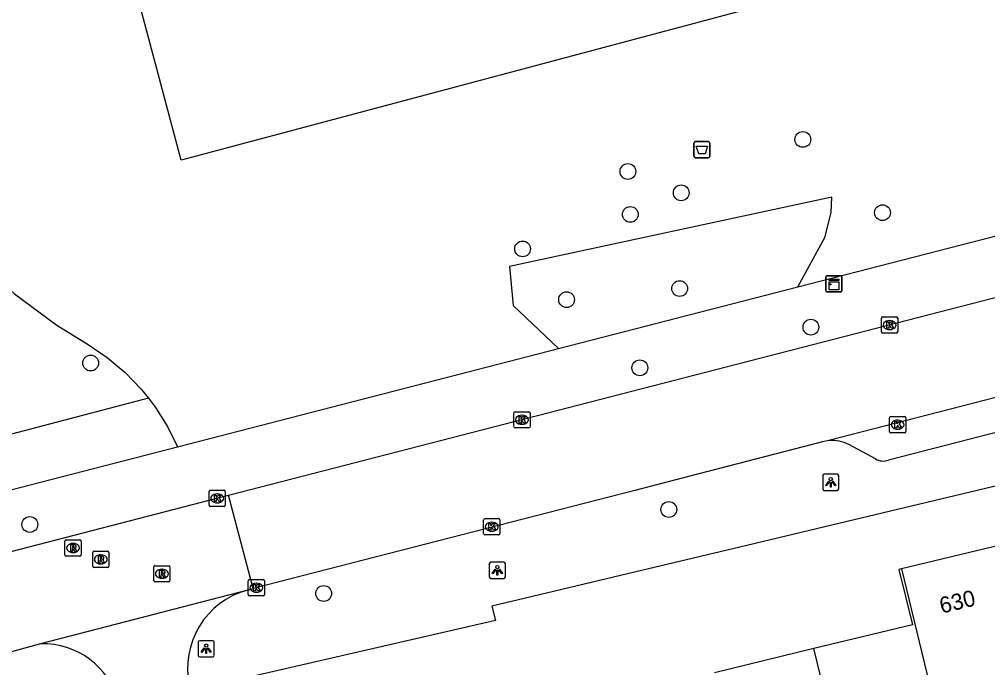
# Model space of a CAD drawing. Extents: x 157793 to 159380, y 380882 to 382313.
# Drawn here: x 158664.6 to 158724.6, y 381293.1 to 381333.3 of the extents above; entities that cross this region are included whole.
import ezdxf

# ---------------------------------------------------------------- set-up
doc = ezdxf.new("R2010")
doc.units = 0
for name, color, linetype in [('IMGEO_Afvalbak', 7, 'Continuous'), ('IMGEO_Boom', 7, 'Continuous'), ('IMGEO_Groenvoorziening', 7, 'Continuous'), ('IMGEO_Kast', 7, 'Continuous'), ('IMGEO_Kolk', 7, 'Continuous'), ('IMGEO_Lichtpunt', 7, 'Continuous'), ('IMGEO_Pand', 7, 'Continuous'), ('IMGEO_Pand_nummerreeks', 7, 'Continuous'), ('IMGEO_Rijbaan_lokaal_gesloten', 7, 'Continuous'), ('IMGEO_Rijbaan_lokaal_open', 7, 'Continuous'), ('IMGEO_Rioolput', 7, 'Continuous'), ('IMGEO_Voetpad_open', 7, 'Continuous')]:
    doc.layers.add(name, color=color, linetype=linetype)

msp = doc.modelspace()

# ---------------------------------------------------------------- linework, layer by layer
at = {"layer": 'IMGEO_Afvalbak'}
for p, q in [((158706.393, 381324.786), (158706.393, 381325.586)), ((158706.393, 381325.586), (158706.393, 381324.786)), ((158706.493, 381325.686), (158707.283, 381325.686)), ((158707.283, 381325.686), (158706.493, 381325.686)), ((158707.383, 381325.586), (158707.383, 381324.786)), ((158707.383, 381324.786), (158707.383, 381325.586)), ((158707.283, 381324.686), (158706.493, 381324.686)), ((158706.493, 381324.686), (158707.283, 381324.686))]:
    msp.add_line(p, q, dxfattribs=at)
msp.add_lwpolyline([(158706.536, 381325.4), (158707.24, 381325.4), (158707.091, 381324.93), (158706.685, 381324.93), (158706.536, 381325.4)], dxfattribs=at)
for centre, start, end in [((158706.493, 381325.586), 90, 180), ((158706.493, 381325.586), 90, 180), ((158707.283, 381325.586), 0, 90), ((158707.283, 381325.586), 360, 90), ((158706.493, 381324.786), 180, 270), ((158706.493, 381324.786), 180, 270), ((158707.283, 381324.786), 270, 0), ((158707.283, 381324.786), 270, 0)]:
    msp.add_arc(centre, 0.1, start, end, dxfattribs=at)
at = {"layer": 'IMGEO_Boom'}
for centre in [(158713.14, 381325.823), (158702.299, 381323.838), (158705.605, 381322.512), (158718.08, 381321.289), (158702.447, 381321.178), (158695.771, 381319.04), (158705.51, 381316.583), (158698.498, 381315.897), (158713.641, 381314.191), (158668.996, 381311.969), (158703.039, 381311.671), (158704.832, 381302.9), (158665.228, 381301.972), (158683.444, 381297.695)]:
    msp.add_circle(centre, 0.489, dxfattribs=at)
at = {"layer": 'IMGEO_Groenvoorziening'}
for points in [[(158724.4, 381337.816), (158674.616, 381324.531), (158668.428, 381347.72), (158718.212, 381361.006), (158724.4, 381337.816)], [(158672.576, 381309.803), (158653.06, 381304.68), (158645.119, 381317.703), (158656.218, 381326.489)], [(158656.218, 381326.489), (158656.274, 381326.359), (158657.867, 381323.531), (158659.748, 381320.885), (158661.895, 381318.45), (158664.285, 381316.252), (158666.892, 381314.317), (158668.836, 381313.126), (158670.029, 381312.319), (158671.13, 381311.391), (158672.129, 381310.354), (158672.576, 381309.803)], [(158712.822, 381316.682), (158714.514, 381319.747), (158714.904, 381321.294), (158714.943, 381322.24), (158694.958, 381317.942), (158695.193, 381315.535), (158697.998, 381312.863)], [(158672.576, 381309.803), (158673.014, 381309.218), (158673.775, 381307.995), (158674.384, 381306.778)]]:
    msp.add_lwpolyline(points, dxfattribs=at)
at = {"layer": 'IMGEO_Kast'}
for p, q in [((158714.568, 381316.455), (158714.568, 381317.296)), ((158714.568, 381317.296), (158714.568, 381316.455)), ((158714.643, 381317.38), (158715.484, 381317.38)), ((158715.484, 381317.38), (158714.643, 381317.38)), ((158715.568, 381317.305), (158715.568, 381316.464)), ((158715.568, 381316.464), (158715.568, 381317.305)), ((158715.493, 381316.38), (158714.652, 381316.38)), ((158714.652, 381316.38), (158715.493, 381316.38))]:
    msp.add_line(p, q, dxfattribs=at)
for points in [[(158714.763, 381317.17), (158715.363, 381317.17), (158715.363, 381317.085), (158714.763, 381317.085), (158714.763, 381317.17)], [(158714.763, 381316.995), (158715.363, 381316.995), (158715.363, 381316.506), (158714.763, 381316.506), (158714.763, 381316.995)]]:
    msp.add_lwpolyline(points, dxfattribs=at)
msp.add_circle((158714.847, 381316.844), 0.0377, dxfattribs=at)
for centre, start, end in [((158714.646, 381317.302), 92.4484, 184.28452), ((158714.646, 381317.302), 92.4484, 184.28452), ((158715.49, 381317.302), 2.4484, 94.28452), ((158715.49, 381317.302), 2.4484, 94.28452), ((158714.646, 381316.458), 182.4484, 274.28452), ((158714.646, 381316.458), 182.4484, 274.28452), ((158715.49, 381316.458), 272.4484, 4.28452), ((158715.49, 381316.458), 272.4484, 4.28452)]:
    msp.add_arc(centre, 0.0779, start, end, dxfattribs=at)
at = {"layer": 'IMGEO_Kolk'}
for p, q in [((158718.019, 381313.898), (158718.019, 381314.75)), ((158718.094, 381314.824), (158718.946, 381314.824)), ((158718.507, 381314.604), (158718.532, 381314.604)), ((158719.02, 381314.75), (158719.02, 381313.898)), ((158718.53, 381314.044), (158718.505, 381314.044)), ((158718.946, 381313.824), (158718.094, 381313.824)), ((158695.23, 381308.029), (158695.23, 381308.881)), ((158695.305, 381308.955), (158696.157, 381308.955)), ((158695.718, 381308.735), (158695.743, 381308.735)), ((158696.231, 381308.881), (158696.231, 381308.029)), ((158718.517, 381307.725), (158718.517, 381308.577)), ((158718.592, 381308.651), (158719.444, 381308.651)), ((158719.518, 381308.577), (158719.518, 381307.725)), ((158696.157, 381307.955), (158695.305, 381307.955)), ((158695.741, 381308.175), (158695.716, 381308.175)), ((158719.005, 381308.431), (158719.03, 381308.431)), ((158719.444, 381307.651), (158718.592, 381307.651)), ((158719.028, 381307.871), (158719.003, 381307.871)), ((158676.343, 381303.161), (158676.343, 381304.013)), ((158676.418, 381304.087), (158677.27, 381304.087)), ((158676.831, 381303.867), (158676.856, 381303.867)), ((158677.344, 381304.013), (158677.344, 381303.161)), ((158676.854, 381303.307), (158676.829, 381303.307)), ((158677.27, 381303.087), (158676.418, 381303.087)), ((158693.358, 381301.404), (158693.358, 381302.256)), ((158693.433, 381302.33), (158694.285, 381302.33)), ((158693.846, 381302.11), (158693.871, 381302.11)), ((158694.359, 381302.256), (158694.359, 381301.404)), ((158694.285, 381301.33), (158693.433, 381301.33)), ((158693.869, 381301.55), (158693.844, 381301.55)), ((158678.769, 381297.625), (158678.769, 381298.477)), ((158678.844, 381298.551), (158679.696, 381298.551)), ((158679.257, 381298.331), (158679.282, 381298.331)), ((158679.77, 381298.477), (158679.77, 381297.625)), ((158679.28, 381297.771), (158679.255, 381297.771)), ((158679.696, 381297.551), (158678.844, 381297.551))]:
    msp.add_line(p, q, dxfattribs=at)
for points in [[(158718.019, 381313.898), (158718.019, 381314.75)], [(158718.094, 381314.824), (158718.946, 381314.824)], [(158718.34, 381314.524), (158718.463, 381314.524), (158718.463, 381314.373), (158718.593, 381314.524), (158718.757, 381314.524), (158718.611, 381314.373), (158718.764, 381314.124), (158718.612, 381314.124), (158718.527, 381314.288), (158718.463, 381314.221), (158718.463, 381314.124), (158718.34, 381314.124), (158718.34, 381314.524)], [(158719.02, 381314.75), (158719.02, 381313.898)], [(158718.946, 381313.824), (158718.094, 381313.824)], [(158695.23, 381308.029), (158695.23, 381308.881)], [(158695.305, 381308.955), (158696.157, 381308.955)], [(158695.551, 381308.655), (158695.674, 381308.655), (158695.674, 381308.504), (158695.804, 381308.655), (158695.968, 381308.655), (158695.822, 381308.504), (158695.975, 381308.255), (158695.823, 381308.255), (158695.738, 381308.419), (158695.674, 381308.352), (158695.674, 381308.255), (158695.551, 381308.255), (158695.551, 381308.655)], [(158696.231, 381308.881), (158696.231, 381308.029)], [(158718.517, 381307.725), (158718.517, 381308.577)], [(158718.592, 381308.651), (158719.444, 381308.651)], [(158719.518, 381308.577), (158719.518, 381307.725)], [(158696.157, 381307.955), (158695.305, 381307.955)], [(158718.838, 381308.351), (158718.961, 381308.351), (158718.961, 381308.2), (158719.091, 381308.351), (158719.255, 381308.351), (158719.109, 381308.2), (158719.262, 381307.951), (158719.11, 381307.951), (158719.025, 381308.115), (158718.961, 381308.048), (158718.961, 381307.951), (158718.838, 381307.951), (158718.838, 381308.351)], [(158719.444, 381307.651), (158718.592, 381307.651)], [(158676.343, 381303.161), (158676.343, 381304.013)], [(158676.418, 381304.087), (158677.27, 381304.087)], [(158676.664, 381303.787), (158676.787, 381303.787), (158676.787, 381303.636), (158676.917, 381303.787), (158677.081, 381303.787), (158676.935, 381303.636), (158677.088, 381303.387), (158676.936, 381303.387), (158676.851, 381303.551), (158676.787, 381303.484), (158676.787, 381303.387), (158676.664, 381303.387), (158676.664, 381303.787)], [(158677.344, 381304.013), (158677.344, 381303.161)], [(158677.27, 381303.087), (158676.418, 381303.087)], [(158693.358, 381301.404), (158693.358, 381302.256)], [(158693.433, 381302.33), (158694.285, 381302.33)], [(158693.679, 381302.03), (158693.802, 381302.03), (158693.802, 381301.879), (158693.932, 381302.03), (158694.096, 381302.03), (158693.95, 381301.879), (158694.103, 381301.63), (158693.951, 381301.63), (158693.866, 381301.794), (158693.802, 381301.727), (158693.802, 381301.63), (158693.679, 381301.63), (158693.679, 381302.03)], [(158694.359, 381302.256), (158694.359, 381301.404)], [(158694.285, 381301.33), (158693.433, 381301.33)], [(158678.769, 381297.625), (158678.769, 381298.477)], [(158678.844, 381298.551), (158679.696, 381298.551)], [(158679.77, 381298.477), (158679.77, 381297.625)], [(158679.09, 381298.251), (158679.213, 381298.251), (158679.213, 381298.1), (158679.343, 381298.251), (158679.507, 381298.251), (158679.361, 381298.1), (158679.514, 381297.851), (158679.362, 381297.851), (158679.277, 381298.015), (158679.213, 381297.948), (158679.213, 381297.851), (158679.09, 381297.851), (158679.09, 381298.251)], [(158679.696, 381297.551), (158678.844, 381297.551)]]:
    msp.add_lwpolyline(points, dxfattribs=at)
for centre, start, end in [((158718.096, 381314.748), 91.55205, 178.44795), ((158718.096, 381314.748), 91.55205, 178.44795), ((158718.944, 381314.748), 1.55205, 88.44795), ((158718.944, 381314.748), 1.55205, 88.44795), ((158718.096, 381313.9), 181.55205, 268.44795), ((158718.096, 381313.9), 181.55205, 268.44795), ((158718.944, 381313.9), 271.55205, 358.44795), ((158718.944, 381313.9), 271.55205, 358.44795), ((158695.307, 381308.879), 91.55205, 178.44795), ((158695.307, 381308.879), 91.55205, 178.44795), ((158696.155, 381308.879), 1.55205, 88.44795), ((158696.155, 381308.879), 1.55205, 88.44795), ((158718.594, 381308.575), 91.55205, 178.44795), ((158718.594, 381308.575), 91.55205, 178.44795), ((158719.442, 381308.575), 1.55205, 88.44795), ((158719.442, 381308.575), 1.55205, 88.44795), ((158695.307, 381308.031), 181.55205, 268.44795), ((158695.307, 381308.031), 181.55205, 268.44795), ((158696.155, 381308.031), 271.55205, 358.44795), ((158696.155, 381308.031), 271.55205, 358.44795), ((158718.594, 381307.727), 181.55205, 268.44795), ((158718.594, 381307.727), 181.55205, 268.44795), ((158719.442, 381307.727), 271.55205, 358.44795), ((158719.442, 381307.727), 271.55205, 358.44795), ((158676.42, 381304.011), 91.55205, 178.44795), ((158676.42, 381304.011), 91.55205, 178.44795), ((158677.268, 381304.011), 1.55205, 88.44795), ((158677.268, 381304.011), 1.55205, 88.44795), ((158676.42, 381303.163), 181.55205, 268.44795), ((158676.42, 381303.163), 181.55205, 268.44795), ((158677.268, 381303.163), 271.55205, 358.44795), ((158677.268, 381303.163), 271.55205, 358.44795), ((158693.435, 381302.254), 91.55205, 178.44795), ((158693.435, 381302.254), 91.55205, 178.44795), ((158694.283, 381302.254), 1.55205, 88.44795), ((158694.283, 381302.254), 1.55205, 88.44795), ((158693.435, 381301.406), 181.55205, 268.44795), ((158693.435, 381301.406), 181.55205, 268.44795), ((158694.283, 381301.406), 271.55205, 358.44795), ((158694.283, 381301.406), 271.55205, 358.44795), ((158678.846, 381298.475), 91.55205, 178.44795), ((158678.846, 381298.475), 91.55205, 178.44795), ((158679.694, 381298.475), 1.55205, 88.44795), ((158679.694, 381298.475), 1.55205, 88.44795), ((158678.846, 381297.627), 181.55205, 268.44795), ((158678.846, 381297.627), 181.55205, 268.44795), ((158679.694, 381297.627), 271.55205, 358.44795), ((158679.694, 381297.627), 271.55205, 358.44795)]:
    msp.add_arc(centre, 0.0765, start, end, dxfattribs=at)
for centre, major_axis, ratio, start_param, end_param in [((158718.506, 381314.324), (-0.387, 0.002), 0.722429, 4.712389, 7.853982), ((158718.531, 381314.324), (-0.39, 0.002), 0.717154, 1.570796, 4.712389), ((158695.717, 381308.455), (-0.387, 0.002), 0.722429, 4.712389, 7.853982), ((158695.742, 381308.455), (-0.39, 0.002), 0.717154, 1.570796, 4.712389), ((158719.004, 381308.151), (-0.387, 0.002), 0.722429, 4.712389, 7.853982), ((158719.029, 381308.151), (-0.39, 0.002), 0.717154, 1.570796, 4.712389), ((158676.83, 381303.587), (-0.387, 0.002), 0.722429, 4.712389, 7.853982), ((158676.855, 381303.587), (-0.39, 0.002), 0.717154, 1.570796, 4.712389), ((158693.845, 381301.83), (-0.387, 0.002), 0.722429, 4.712389, 7.853982), ((158693.87, 381301.83), (-0.39, 0.002), 0.717154, 1.570796, 4.712389), ((158679.256, 381298.051), (-0.387, 0.002), 0.722429, 4.712389, 7.853982), ((158679.281, 381298.051), (-0.39, 0.002), 0.717154, 1.570796, 4.712389)]:
    msp.add_ellipse(centre, major_axis=major_axis, ratio=ratio, start_param=start_param, end_param=end_param, dxfattribs=at)
at = {"layer": 'IMGEO_Lichtpunt'}
for p, q in [((158714.372, 381304.983), (158714.372, 381304.176)), ((158714.372, 381304.983), (158714.372, 381304.176)), ((158715.274, 381305.078), (158714.466, 381305.078)), ((158715.274, 381305.078), (158714.466, 381305.078)), ((158715.368, 381304.176), (158715.368, 381304.983)), ((158715.368, 381304.176), (158715.368, 381304.983)), ((158714.466, 381304.082), (158715.274, 381304.082)), ((158714.466, 381304.082), (158715.274, 381304.082)), ((158693.706, 381299.532), (158693.706, 381298.725)), ((158693.706, 381299.532), (158693.706, 381298.725)), ((158694.608, 381299.627), (158693.8, 381299.627)), ((158694.608, 381299.627), (158693.8, 381299.627)), ((158694.702, 381298.725), (158694.702, 381299.532)), ((158694.702, 381298.725), (158694.702, 381299.532)), ((158693.8, 381298.631), (158694.608, 381298.631)), ((158693.8, 381298.631), (158694.608, 381298.631)), ((158676.563, 381294.768), (158675.755, 381294.768)), ((158676.563, 381294.768), (158675.755, 381294.768)), ((158675.661, 381294.673), (158675.661, 381293.866)), ((158675.661, 381294.673), (158675.661, 381293.866)), ((158676.657, 381293.866), (158676.657, 381294.673)), ((158676.657, 381293.866), (158676.657, 381294.673)), ((158675.755, 381293.772), (158676.563, 381293.772)), ((158675.755, 381293.772), (158676.563, 381293.772))]:
    msp.add_line(p, q, dxfattribs=at)
for points in [[(158714.746, 381304.647), (158714.785, 381304.619), (158714.597, 381304.357), (158714.559, 381304.384), (158714.746, 381304.647)], [(158714.848, 381304.599), (158714.895, 381304.599), (158714.895, 381304.277), (158714.848, 381304.277), (158714.848, 381304.599)], [(158714.958, 381304.619), (158714.996, 381304.646), (158715.183, 381304.384), (158715.144, 381304.356), (158714.958, 381304.619)], [(158694.08, 381299.196), (158694.119, 381299.168), (158693.931, 381298.906), (158693.893, 381298.933), (158694.08, 381299.196)], [(158694.182, 381299.148), (158694.229, 381299.148), (158694.229, 381298.826), (158694.182, 381298.826), (158694.182, 381299.148)], [(158694.292, 381299.168), (158694.33, 381299.195), (158694.517, 381298.933), (158694.478, 381298.905), (158694.292, 381299.168)], [(158676.035, 381294.337), (158676.074, 381294.309), (158675.886, 381294.047), (158675.848, 381294.074), (158676.035, 381294.337)], [(158676.137, 381294.289), (158676.184, 381294.289), (158676.184, 381293.967), (158676.137, 381293.967), (158676.137, 381294.289)], [(158676.247, 381294.309), (158676.285, 381294.336), (158676.472, 381294.074), (158676.433, 381294.046), (158676.247, 381294.309)]]:
    msp.add_lwpolyline(points, dxfattribs=at)
for centre in [(158714.871, 381304.781), (158694.205, 381299.33), (158676.16, 381294.471)]:
    msp.add_circle(centre, 0.0994, dxfattribs=at)
for centre, start, end in [((158714.466, 381304.983), 90, 180), ((158714.466, 381304.983), 90, 180), ((158715.274, 381304.983), 0, 90), ((158715.274, 381304.983), 0, 90), ((158714.466, 381304.176), 180, 270), ((158714.466, 381304.176), 180, 270), ((158715.274, 381304.176), 270, 0), ((158715.274, 381304.176), 270, 360), ((158693.8, 381299.532), 90, 180), ((158693.8, 381299.532), 90, 180), ((158694.608, 381299.532), 0, 90), ((158694.608, 381299.532), 0, 90), ((158693.8, 381298.725), 180, 270), ((158693.8, 381298.725), 180, 270), ((158694.608, 381298.725), 270, 0), ((158694.608, 381298.725), 270, 360), ((158675.755, 381294.673), 90, 180), ((158675.755, 381294.673), 90, 180), ((158676.563, 381294.673), 0, 90), ((158676.563, 381294.673), 0, 90), ((158675.755, 381293.866), 180, 270), ((158675.755, 381293.866), 180, 270), ((158676.563, 381293.866), 270, 0), ((158676.563, 381293.866), 270, 360)]:
    msp.add_arc(centre, 0.0946, start, end, dxfattribs=at)
at = {"layer": 'IMGEO_Pand'}
for points in [[(158725.364, 381300.693), (158719.256, 381299.213)], [(158719.256, 381299.213), (158719.099, 381299.175), (158719.928, 381295.758), (158713.829, 381294.28)], [(158719.256, 381299.213), (158721.302, 381290.776)], [(158713.829, 381294.28), (158707.672, 381292.787)], [(158715.881, 381285.837), (158713.829, 381294.28)]]:
    msp.add_lwpolyline(points, dxfattribs=at)
at = {"layer": 'IMGEO_Rijbaan_lokaal_gesloten'}
for points in [[(158677.535, 381303.782), (158738.035, 381319.375)], [(158739.374, 381313.506), (158714.757, 381307.175)], [(158714.757, 381307.175), (158714.356, 381307.082), (158706.701, 381305.1), (158702.652, 381304.063), (158695.077, 381302.12), (158679.064, 381297.998)], [(158679.064, 381297.998), (158677.535, 381303.782)]]:
    msp.add_lwpolyline(points, dxfattribs=at)
at = {"layer": 'IMGEO_Rijbaan_lokaal_open'}
for points in [[(158662.382, 381299.863), (158677.535, 381303.782)], [(158678.731, 381297.907), (158665.898, 381294.577)], [(158678.731, 381297.907), (158679.064, 381297.998)], [(158665.898, 381294.577), (158663.869, 381294.026)]]:
    msp.add_lwpolyline(points, dxfattribs=at)
for centre, radius, start, end in [((158680.015, 381293.068), 5.006, 104.85682, 192.55267), ((158666.049, 381289.747), 4.833, 14.85765, 91.79137)]:
    msp.add_arc(centre, radius, start, end, dxfattribs=at)
at = {"layer": 'IMGEO_Rioolput'}
for p, q in [((158667.405, 381300.086), (158667.405, 381300.938)), ((158667.48, 381301.012), (158668.332, 381301.012)), ((158667.893, 381300.792), (158667.918, 381300.792)), ((158668.406, 381300.938), (158668.406, 381300.086)), ((158667.916, 381300.232), (158667.891, 381300.232)), ((158669.128, 381299.383), (158669.128, 381300.235)), ((158669.203, 381300.309), (158670.055, 381300.309)), ((158670.129, 381300.235), (158670.129, 381299.383)), ((158668.332, 381300.012), (158667.48, 381300.012)), ((158669.639, 381299.529), (158669.614, 381299.529)), ((158669.616, 381300.089), (158669.641, 381300.089)), ((158670.055, 381299.309), (158669.203, 381299.309)), ((158672.913, 381298.492), (158672.913, 381299.344)), ((158672.988, 381299.418), (158673.84, 381299.418)), ((158673.401, 381299.198), (158673.426, 381299.198)), ((158673.914, 381299.344), (158673.914, 381298.492)), ((158673.84, 381298.418), (158672.988, 381298.418)), ((158673.424, 381298.638), (158673.399, 381298.638))]:
    msp.add_line(p, q, dxfattribs=at)
for points in [[(158667.405, 381300.086), (158667.405, 381300.938)], [(158667.48, 381301.012), (158668.332, 381301.012)], [(158667.994, 381300.71), (158667.742, 381300.712), (158667.742, 381300.312)], [(158668.406, 381300.938), (158668.406, 381300.086)], [(158667.742, 381300.312), (158667.866, 381300.312), (158667.866, 381300.474), (158667.877, 381300.474)], [(158667.92, 381300.631), (158667.866, 381300.631), (158667.866, 381300.55)], [(158667.866, 381300.55), (158667.918, 381300.55)], [(158667.924, 381300.445), (158667.995, 381300.312), (158668.135, 381300.312), (158668.07, 381300.438)], [(158669.128, 381299.383), (158669.128, 381300.235)], [(158669.203, 381300.309), (158670.055, 381300.309)], [(158670.129, 381300.235), (158670.129, 381299.383)], [(158668.332, 381300.012), (158667.48, 381300.012)], [(158669.717, 381300.007), (158669.465, 381300.009), (158669.465, 381299.609)], [(158669.465, 381299.609), (158669.589, 381299.609), (158669.589, 381299.771), (158669.6, 381299.771)], [(158669.643, 381299.928), (158669.589, 381299.928), (158669.589, 381299.847)], [(158669.589, 381299.847), (158669.641, 381299.847)], [(158669.647, 381299.742), (158669.718, 381299.609), (158669.858, 381299.609), (158669.793, 381299.735)], [(158670.055, 381299.309), (158669.203, 381299.309)], [(158672.913, 381298.492), (158672.913, 381299.344)], [(158672.988, 381299.418), (158673.84, 381299.418)], [(158673.502, 381299.116), (158673.25, 381299.118), (158673.25, 381298.718)], [(158673.428, 381299.037), (158673.374, 381299.037), (158673.374, 381298.956)], [(158673.374, 381298.956), (158673.426, 381298.956)], [(158673.914, 381299.344), (158673.914, 381298.492)], [(158673.84, 381298.418), (158672.988, 381298.418)], [(158673.25, 381298.718), (158673.374, 381298.718), (158673.374, 381298.88), (158673.385, 381298.88)], [(158673.432, 381298.851), (158673.503, 381298.718), (158673.643, 381298.718), (158673.578, 381298.844)]]:
    msp.add_lwpolyline(points, dxfattribs=at)
for centre, radius, start, end in [((158667.482, 381300.936), 0.0765, 91.55205, 178.44795), ((158667.482, 381300.936), 0.0765, 91.55205, 178.44795), ((158667.993, 381300.6), 0.109, 350.36119, 89.41601), ((158668.33, 381300.936), 0.0765, 1.55205, 88.44795), ((158668.33, 381300.936), 0.0765, 1.55205, 88.44795), ((158667.876, 381300.421), 0.0533, 26.02933, 88.69889), ((158667.902, 381300.739), 0.19, 274.7715, 282.96867), ((158667.926, 381300.535), 0.0964, 77.00612, 93.18647), ((158667.94, 381300.592), 0.0378, 276.66336, 79.67722), ((158667.991, 381300.6), 0.112, 277.58423, 350.98172), ((158667.975, 381300.385), 0.108, 29.51342, 73.79051), ((158669.205, 381300.233), 0.0765, 91.55205, 178.44795), ((158669.205, 381300.233), 0.0765, 91.55205, 178.44795), ((158670.053, 381300.233), 0.0765, 1.55205, 88.44795), ((158670.053, 381300.233), 0.0765, 1.55205, 88.44795), ((158667.482, 381300.088), 0.0765, 181.55205, 268.44795), ((158667.482, 381300.088), 0.0765, 181.55205, 268.44795), ((158668.33, 381300.088), 0.0765, 271.55205, 358.44795), ((158668.33, 381300.088), 0.0765, 271.55205, 358.44795), ((158669.599, 381299.718), 0.0533, 26.02933, 88.69889), ((158669.625, 381300.036), 0.19, 274.7715, 282.96867), ((158669.649, 381299.832), 0.0964, 77.00612, 93.18647), ((158669.663, 381299.889), 0.0378, 276.66336, 79.67722), ((158669.716, 381299.897), 0.109, 350.36119, 89.41601), ((158669.714, 381299.897), 0.112, 277.58423, 350.98172), ((158669.698, 381299.682), 0.108, 29.51342, 73.79051), ((158669.205, 381299.385), 0.0765, 181.55205, 268.44795), ((158669.205, 381299.385), 0.0765, 181.55205, 268.44795), ((158670.053, 381299.385), 0.0765, 271.55205, 358.44795), ((158670.053, 381299.385), 0.0765, 271.55205, 358.44795), ((158672.99, 381299.342), 0.0765, 91.55205, 178.44795), ((158672.99, 381299.342), 0.0765, 91.55205, 178.44795), ((158673.41, 381299.145), 0.19, 274.7715, 282.96867), ((158673.434, 381298.941), 0.0964, 77.00612, 93.18647), ((158673.448, 381298.998), 0.0378, 276.66336, 79.67722), ((158673.501, 381299.006), 0.109, 350.36119, 89.41601), ((158673.499, 381299.006), 0.112, 277.58423, 350.98172), ((158673.838, 381299.342), 0.0765, 1.55205, 88.44795), ((158673.838, 381299.342), 0.0765, 1.55205, 88.44795), ((158672.99, 381298.494), 0.0765, 181.55205, 268.44795), ((158672.99, 381298.494), 0.0765, 181.55205, 268.44795), ((158673.384, 381298.827), 0.0533, 26.02933, 88.69889), ((158673.483, 381298.791), 0.108, 29.51342, 73.79051), ((158673.838, 381298.494), 0.0765, 271.55205, 358.44795), ((158673.838, 381298.494), 0.0765, 271.55205, 358.44795)]:
    msp.add_arc(centre, radius, start, end, dxfattribs=at)
for centre, major_axis, ratio, start_param, end_param in [((158667.892, 381300.512), (-0.387, 0.002), 0.722429, 4.712389, 7.853982), ((158667.917, 381300.512), (-0.39, 0.002), 0.717154, 1.570796, 4.712389), ((158669.615, 381299.809), (-0.387, 0.002), 0.722429, 4.712389, 7.853982), ((158669.64, 381299.809), (-0.39, 0.002), 0.717154, 1.570796, 4.712389), ((158673.4, 381298.918), (-0.387, 0.002), 0.722429, 4.712389, 7.853982), ((158673.425, 381298.918), (-0.39, 0.002), 0.717154, 1.570796, 4.712389)]:
    msp.add_ellipse(centre, major_axis=major_axis, ratio=ratio, start_param=start_param, end_param=end_param, dxfattribs=at)
at = {"layer": 'IMGEO_Voetpad_open'}
for points in [[(158712.822, 381316.682), (158735.17, 381322.441)], [(158697.998, 381312.863), (158712.822, 381316.682)], [(158674.384, 381306.778), (158697.998, 381312.863)], [(158736.833, 381310.675), (158718.454, 381305.96)], [(158745.268, 381304.094), (158744.131, 381308.881), (158714.509, 381301.828), (158709.669, 381300.675), (158702.264, 381298.912), (158696.818, 381297.616), (158693.859, 381296.911), (158694.082, 381296.018), (158678.547, 381292.443), (158679.178, 381289.904), (158679.54, 381288.53)], [(158652.985, 381301.264), (158674.384, 381306.778)], [(158717.641, 381306.032), (158715.984, 381306.918)]]:
    msp.add_lwpolyline(points, dxfattribs=at)
for centre, radius, start, end in [((158714.929, 381304.94), 2.241, 61.92979, 94.41059), ((158718.124, 381306.858), 0.957, 239.69197, 290.18611)]:
    msp.add_arc(centre, radius, start, end, dxfattribs=at)

# ---------------------------------------------------------------- texts
at = {"layer": 'IMGEO_Pand_nummerreeks'}
msp.add_text('630', height=1, rotation=13.62494, dxfattribs=at).set_placement((158721.747, 381296.442))

doc.saveas('drawing.dxf')
